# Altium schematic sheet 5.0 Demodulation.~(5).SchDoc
size A4; SheetNumber: 5; SheetTotal: 6
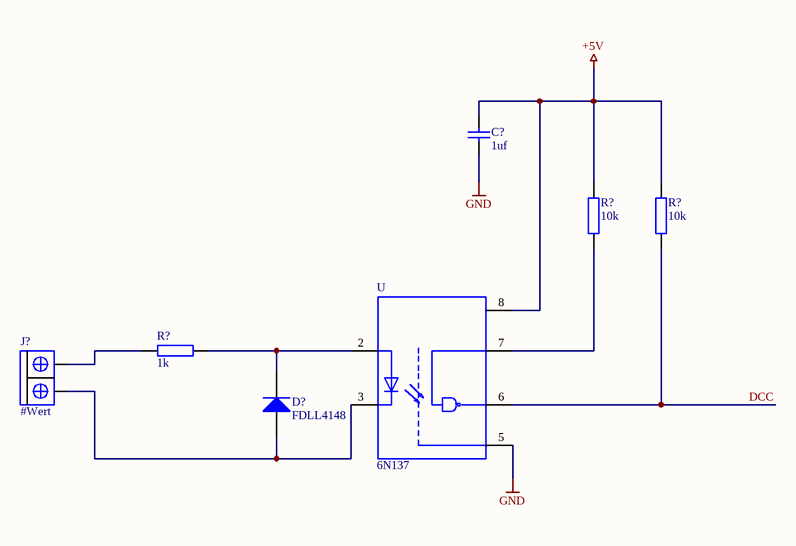
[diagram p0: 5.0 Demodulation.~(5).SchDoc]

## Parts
(Parts that share a designator on the sheet are numbered #1, #2 ... from top to bottom, then left to right.)
C?  1uf  [C_SMD_0805]
D?  FDLL4148  [D_SMD_1206]
J?  #Wert  [J_THT_Printklemme 2x]
R?#1  10k  [R_SMD_0805]
R?#2  10k  [R_SMD_0805]
R?#3  1k  [R_SMD_0805]
U  6N137  [DIP762W50P254L977H451Q8]

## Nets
+5V: C?.1 R?#1.2 R?#2.2 U.8(VCC)
GND: C?.2 U.5(GND)
DCC: R?#2.1 U.6(VO)
NetD?_1: D?.1(A) J?.1 U.3(C)
NetD?_2: D?.2(K) R?#3.2 U.2(A)
NetJ?_2: J?.2 R?#3.1
NetR?#1_1: R?#1.1 U.7(VE)

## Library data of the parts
C? = C_SMD_KO: Kondensator SMD Universal, Keramik, Folie, usw.
D? = D_SMD_Silizium: Diode SMD Silizium; Spannung For.: 0,7V
J? = J_THT_Printklemme 2x: Printklemme
R?#1-R?#3 = R_SMD_Widerstand: Widerstand SMD
U = 6N137: Optoaislador de salida lÃ³gica 10Mbps Open Collector 5000Vrms 1 Channel 5kV / Âµs CMTI 8-DIP; MF: Everlight Electronics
